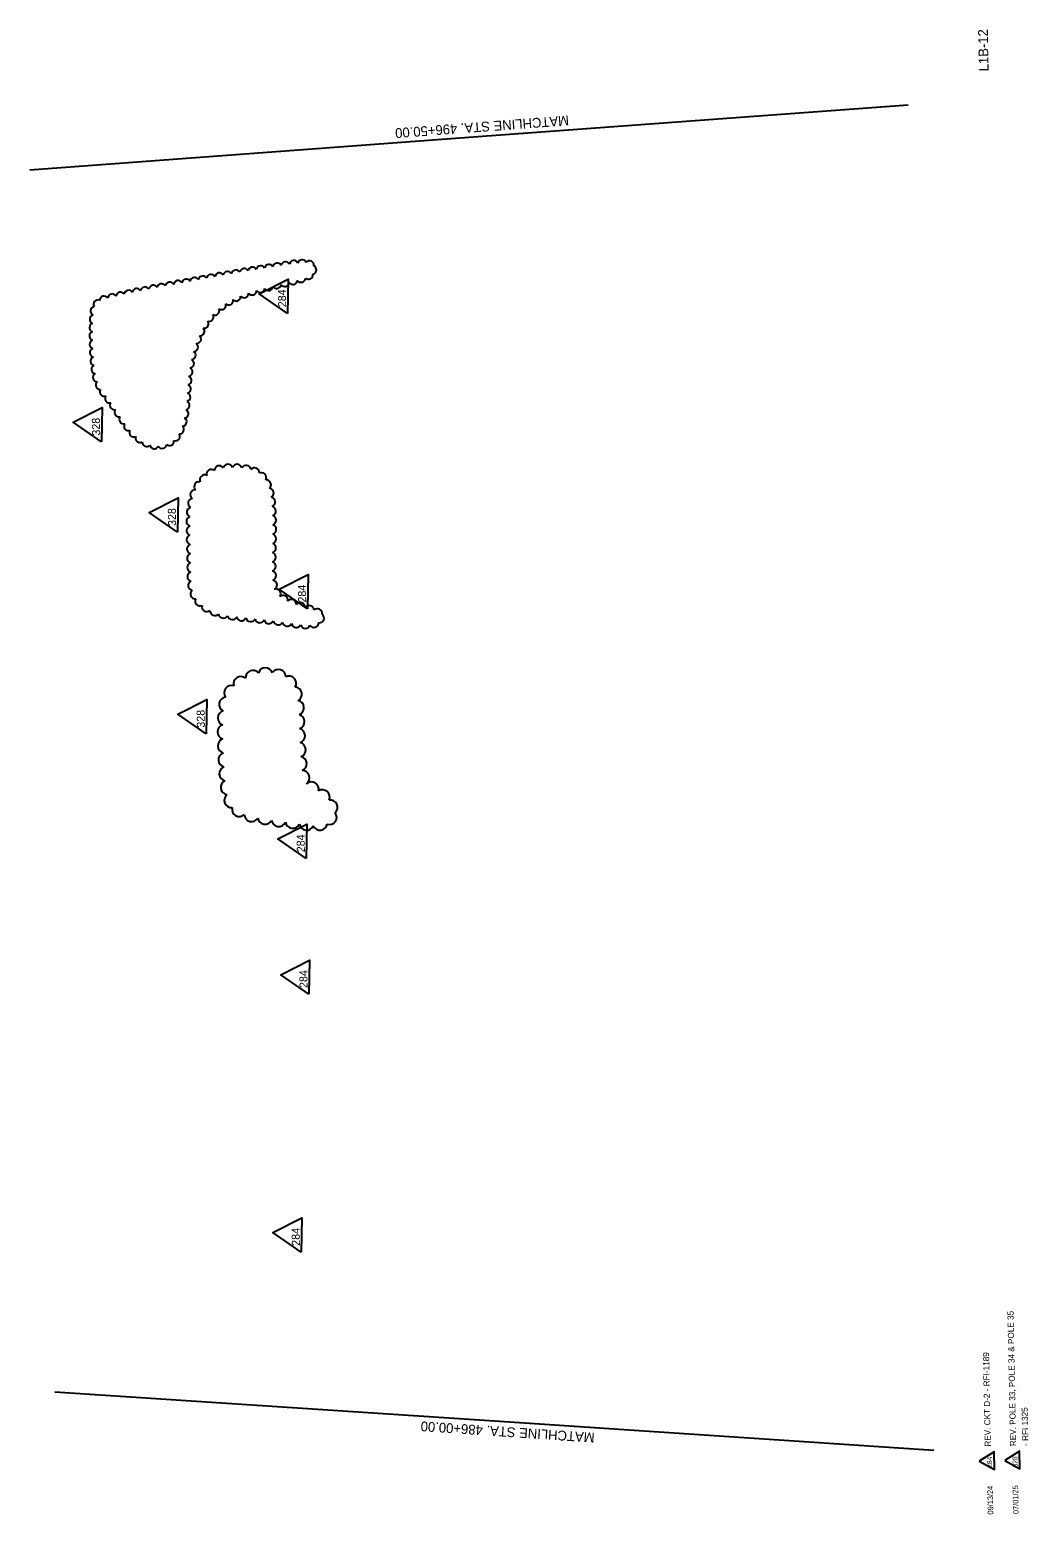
# Model space of a CAD drawing. Extents: x 930885 to 931702, y 624671 to 625884.
import ezdxf

# ---------------------------------------------------------------- set-up
doc = ezdxf.new("R2010")
doc.units = 0
for name, color, linetype in [('ActivePointCell_dp', 7, 'Continuous'), ('Cloud_dp', 7, 'Continuous'), ('CurbRampWarning', 7, 'Continuous'), ('TextMisc', 7, 'Continuous')]:
    doc.layers.add(name, color=color, linetype=linetype)

msp = doc.modelspace()

# ---------------------------------------------------------------- linework, layer by layer
at = {"layer": 'Cloud_dp'}
for points in [[(931096.1, 625652.5), (931073, 625668.5), (931096.7, 625680.5)], [(930944.1, 625547.6), (930921, 625563.6), (930944.7, 625575.6)], [(931006.2, 625473.8), (930983.1, 625489.8), (931006.8, 625501.8)], [(931112.5, 625411.2), (931089.4, 625427.2), (931113.1, 625439.2)], [(931029.7, 625309), (931006.6, 625325), (931030.3, 625337)], [(931111.5, 625207.2), (931088.3, 625223.2), (931112, 625235.2)], [(931113.7, 625096.2), (931090.6, 625112.2), (931114.2, 625124.2)], [(931107.3, 624885.6), (931084.2, 624901.6), (931107.9, 624913.6)], [(931682.3, 624715.2), (931694.8, 624708.4), (931694.5, 624722.9)], [(931661.5, 624714.8), (931674, 624708), (931673.7, 624722.5)]]:
    msp.add_lwpolyline(points, close=True, dxfattribs=at)
for centre, radius, start, end in [((931087.8, 625690.1), 3.6, 26.3521, 171.3521), ((931094.6, 625691.1), 3.6, 25.8316, 170.8316), ((931101.4, 625692.1), 3.6, 24.986, 169.986), ((931108.2, 625692.8), 3.6, 23.1991, 168.1991), ((931114.2, 625691.8), 3.6, 352.6343, 137.6343), ((931020.2, 625678.3), 3.6, 27.9906, 172.9906), ((931027, 625679.5), 3.6, 27.911, 172.911), ((931033.7, 625680.8), 3.6, 27.8309, 172.8309), ((931040.5, 625682), 3.6, 27.739, 172.739), ((931047.2, 625683.2), 3.6, 27.6339, 172.6339), ((931054, 625684.4), 3.6, 27.5122, 172.5122), ((931060.8, 625685.6), 3.6, 27.3689, 172.3689), ((931067.5, 625686.8), 3.6, 27.1968, 172.1968), ((931074.3, 625687.9), 3.6, 26.9846, 171.9846), ((931081.1, 625689), 3.6, 26.7141, 171.7141), ((931107.2, 625681.5), 3.6, 213.2737, 358.2737), ((931113.3, 625683.9), 3.6, 225.3617, 10.3617), ((931116.2, 625688.1), 3.6, 280.1968, 65.1968), ((930959.6, 625666.3), 3.6, 30.0337, 175.0337), ((930966.3, 625667.8), 3.6, 29.4823, 174.4823), ((930973, 625669.2), 3.6, 29.1082, 174.1082), ((930979.7, 625670.5), 3.6, 28.8328, 173.8328), ((930986.5, 625671.9), 3.6, 28.6191, 173.6191), ((930993.2, 625673.2), 3.6, 28.4471, 173.4471), ((931000, 625674.5), 3.6, 28.3047, 173.3047), ((931006.7, 625675.8), 3.6, 28.1844, 173.1844), ((931013.5, 625677), 3.6, 28.0809, 173.0809), ((931060.7, 625668.9), 3.6, 218.3415, 3.3415), ((931067.3, 625671.2), 3.6, 214.6661, 359.6661), ((931073.9, 625673.1), 3.6, 211.8549, 356.8549), ((931080.6, 625674.7), 3.6, 211.4576, 356.4576), ((931087.3, 625676.4), 3.6, 211.4576, 356.4576), ((931093.9, 625678.1), 3.6, 211.4576, 356.4576), ((931100.6, 625679.7), 3.6, 211.4576, 356.4576), ((930938.8, 625654.5), 3.6, 99.819, 244.819), ((930941.2, 625659.9), 3.6, 65.7794, 210.7794), ((930946.3, 625663), 3.6, 33.2335, 178.2335), ((930952.9, 625664.8), 3.6, 30.972, 175.972), ((931042.3, 625659.2), 3.6, 233.6591, 18.6591), ((931048.2, 625663), 3.6, 227.7365, 12.7365), ((931054.3, 625666.2), 3.6, 222.6606, 7.6606), ((930938.1, 625647.7), 3.6, 104.4869, 249.4869), ((931028.1, 625643.9), 3.6, 255.6999, 40.6999), ((931032.1, 625649.6), 3.6, 247.9757, 32.9757), ((931036.9, 625654.7), 3.6, 240.4455, 25.4455), ((930937.9, 625640.9), 3.6, 106.5759, 251.5759), ((930937.9, 625634.1), 3.6, 107.8311, 252.8311), ((931021.9, 625631.5), 3.6, 265.8828, 50.8828), ((931024.7, 625637.8), 3.6, 261.2853, 46.2853), ((930938, 625627.2), 3.6, 108.8163, 253.8163), ((930938.2, 625620.4), 3.6, 110.375, 255.375), ((931017.6, 625618.3), 3.6, 273.4879, 58.4879), ((931019.5, 625624.9), 3.6, 269.9335, 54.9335), ((930938.7, 625613.6), 3.6, 112.5634, 257.5634), ((930939.5, 625606.8), 3.6, 115.7865, 260.7865), ((931016.2, 625611.5), 3.6, 276.606, 61.606), ((930940.8, 625600.2), 3.6, 121.1745, 266.1745), ((930943, 625593.9), 3.6, 132.6216, 277.6216), ((931014.2, 625597.8), 3.6, 281.7673, 66.7673), ((931015, 625604.7), 3.6, 279.3476, 64.3476), ((930946.4, 625588.4), 3.6, 146.3688, 291.3688), ((930950.7, 625582.9), 3.6, 143.7824, 288.7824), ((931013.2, 625584.1), 3.6, 283.6241, 68.6241), ((931013.6, 625590.9), 3.6, 283.9032, 68.9032), ((930954.7, 625577.3), 3.6, 141.9616, 286.9616), ((930958.5, 625571.5), 3.6, 140.7139, 285.7139), ((931011.6, 625570.6), 3.6, 277.8101, 62.8101), ((931012.6, 625577.3), 3.6, 281.1778, 66.1778), ((930962.3, 625565.8), 3.6, 140.8458, 285.8458), ((930966.2, 625560.3), 3.6, 144.8417, 289.8417), ((931008, 625557.6), 3.6, 264.554, 49.554), ((931010.2, 625563.9), 3.6, 272.8162, 57.8162), ((930970.5, 625555.1), 3.6, 150.7177, 295.7177), ((930975.5, 625550.6), 3.6, 159.4095, 304.4095), ((930981.1, 625547.2), 3.6, 172.776, 317.776), ((930999.8, 625548), 3.6, 225.0593, 10.0593), ((931004.7, 625552), 3.6, 248.7535, 33.7535), ((930987.3, 625545.5), 3.6, 191.303, 336.303), ((930993.7, 625545.8), 3.6, 209.8393, 354.8393), ((931034, 625521.1), 3.95, 49.3658, 194.3658), ((931040.5, 625524.1), 3.95, 34.4268, 179.4268), ((931047.6, 625525.3), 3.95, 20.998, 165.998), ((931055, 625525.3), 3.95, 14.1816, 159.1816), ((931062.3, 625524.4), 3.95, 6.8112, 151.8112), ((931069.3, 625522.4), 3.95, 354.6671, 139.6671), ((931023.9, 625510.9), 3.95, 75.6081, 220.6081), ((931028.4, 625516.6), 3.95, 62.7191, 207.7191), ((931074.9, 625518.4), 3.95, 331.0606, 116.0606), ((931078.8, 625512.6), 3.95, 311.1667, 96.1667), ((931018.8, 625497.4), 3.95, 96.3984, 241.3984), ((931020.7, 625504.4), 3.95, 87.4668, 232.4668), ((931081, 625505.7), 3.95, 299.4392, 84.4392), ((931082.2, 625498.4), 3.95, 293.5128, 78.5128), ((931017.8, 625490.1), 3.95, 103.0003, 248.0003), ((931082.8, 625490.9), 3.95, 290.5175, 75.5175), ((931083, 625483.5), 3.95, 288.6544, 73.6544), ((931017.5, 625482.6), 3.95, 107.7116, 252.7116), ((931017.6, 625475.1), 3.95, 108.6383, 253.6383), ((931083.1, 625476), 3.95, 287.3547, 72.3547), ((931017.7, 625467.6), 3.95, 108.6383, 253.6383), ((931017.9, 625460.1), 3.95, 108.6383, 253.6383), ((931082.8, 625460.9), 3.95, 286.0295, 71.0295), ((931083, 625468.4), 3.95, 286.3827, 71.3827), ((931018, 625452.5), 3.95, 108.6383, 253.6383), ((931082.7, 625453.4), 3.95, 286.8154, 71.8154), ((931018.2, 625445), 3.95, 108.6383, 253.6383), ((931018.3, 625437.5), 3.95, 108.6383, 253.6383), ((931082.7, 625445.8), 3.95, 288.0459, 73.0459), ((931082.9, 625438.2), 3.95, 290.2089, 75.2089), ((931018.9, 625430.1), 3.95, 115.3249, 260.3249), ((931020.9, 625423.3), 3.95, 131.6074, 276.6074), ((931083.7, 625430.6), 3.95, 295.9515, 80.9515), ((931086.7, 625423.4), 3.95, 324.59, 109.59), ((931024.7, 625417.4), 3.95, 149.8847, 294.8847), ((931092.6, 625418.2), 3.95, 347.337, 132.337), ((931099.5, 625414.8), 3.95, 355.8591, 140.8591), ((931106.6, 625412.2), 3.95, 358.7863, 143.7863), ((931030.2, 625412.8), 3.95, 165.6075, 310.6075), ((931036.7, 625409.6), 3.95, 176.9494, 321.9494), ((931043.8, 625407.5), 3.95, 184.7877, 329.7877), ((931051.1, 625406.2), 3.95, 190.2584, 335.2584), ((931058.5, 625405.3), 3.95, 191.6433, 336.6433), ((931066, 625404.6), 3.95, 191.4018, 336.4018), ((931073.5, 625403.7), 3.95, 191.093, 336.093), ((931081, 625402.9), 3.95, 190.6787, 335.6787), ((931113.9, 625409.9), 3.95, 1.9253, 146.9253), ((931120.7, 625407.3), 3.95, 351.3831, 136.3831), ((931122.1, 625403.7), 3.95, 265.113, 50.113), ((931088.5, 625401.9), 3.95, 190.0801, 335.0801), ((931096, 625400.9), 3.95, 189.0992, 334.0992), ((931103.4, 625399.7), 3.95, 188.4229, 333.4229), ((931110.8, 625399), 3.95, 195.0361, 340.0361), ((931117.8, 625399.9), 3.95, 214.0344, 359.0344), ((931058, 625349.8), 5.99, 50.758, 195.758), ((931067.8, 625354.9), 5.99, 39.1427, 184.1427), ((931078.2, 625357), 5.99, 19.247, 164.247), ((931088.8, 625355.6), 5.99, 0.1313, 145.1313), ((931097.3, 625350.2), 5.99, 330.6168, 115.6168), ((931050.3, 625342.5), 5.99, 71.058, 216.058), ((931102, 625341.3), 5.99, 299.7134, 84.7134), ((931046.3, 625333.1), 5.99, 98.0121, 243.0121), ((931103.6, 625330.3), 5.99, 291.9303, 76.9303), ((931045.2, 625321.9), 5.99, 105.5168, 250.5168), ((931104.2, 625318.9), 5.99, 288.9684, 73.9684), ((931045, 625310.6), 5.99, 107.6958, 252.6958), ((931045.2, 625299.2), 5.99, 109.3509, 254.3509), ((931104.5, 625307.5), 5.99, 289.4893, 74.4893), ((931045.7, 625287.8), 5.99, 110.6426, 255.6426), ((931105.1, 625296), 5.99, 290.6715, 75.6715), ((931046.4, 625276.5), 5.99, 111.728, 256.728), ((931105.9, 625284.6), 5.99, 292.9268, 77.9268), ((931047.6, 625265.2), 5.99, 115.8641, 260.8641), ((931108.3, 625273.1), 5.99, 305.1619, 90.1619), ((931115.8, 625263.7), 5.99, 347.2128, 132.2128), ((931050.5, 625254.7), 5.99, 129.5146, 274.5146), ((931124.7, 625257.3), 5.99, 335.9474, 120.9474), ((931056.8, 625247.4), 5.99, 167.2537, 312.2537), ((931130.4, 625240.9), 5.99, 252.0285, 37.0285), ((931131, 625248.9), 6, 313.6148, 98.6148), ((931066.8, 625243.3), 5.99, 183.5943, 328.5943), ((931077.9, 625241), 5.99, 187.738, 332.738), ((931089.1, 625239.3), 5.99, 189.7663, 334.7663), ((931100.4, 625237.8), 5.99, 190.117, 335.117), ((931111.8, 625236.3), 5.99, 190.117, 335.117), ((931122.7, 625236.3), 5.99, 204.7543, 349.7543)]:
    msp.add_arc(centre, radius, start, end, dxfattribs=at)
at = {"layer": 'TextMisc'}
for points in [[(931603.5, 625822.7), (931244.5, 625796.1), (930885.5, 625769.4)], [(931624.5, 624723.5), (931265.3, 624747.4), (930906.1, 624771.2)]]:
    msp.add_lwpolyline(points, dxfattribs=at)

# ---------------------------------------------------------------- texts
at = {"layer": 'ActivePointCell_dp'}
msp.add_text('L1B-12', height=8, rotation=91.1383, dxfattribs=at).set_placement((931669.2, 625850.3))
at = {"layer": 'Cloud_dp'}
for s, height, p in [('284', 6.54, (931095.1, 625657.6)), ('328', 6.54, (930943.1, 625552.7)), ('328', 6.54, (931005.2, 625478.9)), ('284', 6.54, (931111.5, 625416.3)), ('328', 6.54, (931028.7, 625314.1)), ('284', 6.54, (931110.4, 625212.3)), ('284', 6.54, (931112.6, 625101.4)), ('284', 6.54, (931106.3, 624890.8)), ('284', 3.94, (931672, 624709.4)), ('328', 3.94, (931692.8, 624709.7))]:
    msp.add_text(s, height=height, rotation=91.1383, dxfattribs=at).set_placement(p)
at = {"layer": 'CurbRampWarning'}
for s, height, p in [('REV. POLE 33, POLE 34 & POLE 35 ', 4.99, (931691.7, 624727.1)), ('REV. CKT D-2 - RFI-1189', 4.99, (931671, 624726.7)), ('- RFI 1325', 4.99, (931701.7, 624727.3)), ('09/13/24', 4.52, (931673, 624671.2)), ('07/01/25', 4.52, (931693.7, 624671.6))]:
    msp.add_text(s, height=height, rotation=91.1383, dxfattribs=at).set_placement(p)
at = {"layer": 'TextMisc'}
for s, rotation, p in [('MATCHLINE STA. 496+50.00', 184.2492, (931325.9, 625814.2)), ('MATCHLINE STA. 486+00.00', 176.2013, (931347.4, 624737.9))]:
    msp.add_text(s, height=8, rotation=rotation, dxfattribs=at).set_placement(p)

doc.saveas('drawing.dxf')
